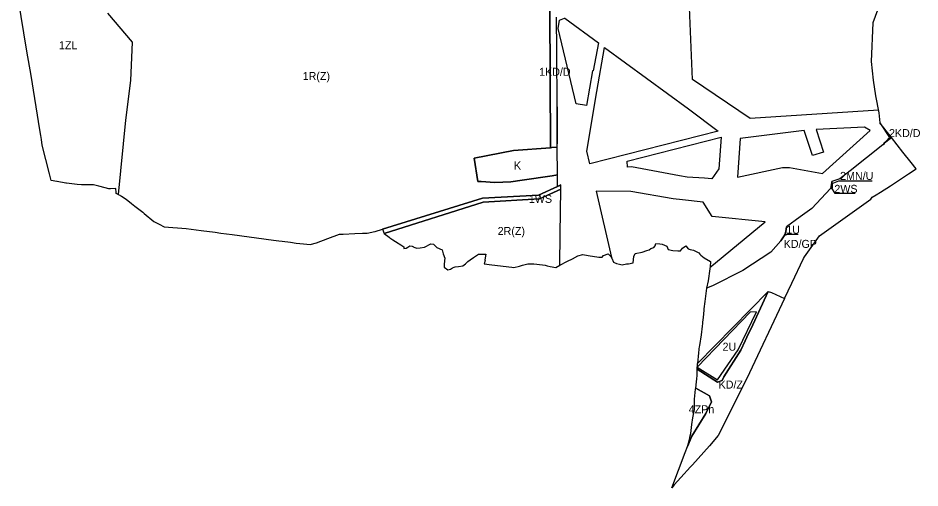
# Model space of a CAD drawing. Extents: x 7416449 to 7417931, y 5540122 to 5541628.
# Drawn here: x 7416476 to 7417829, y 5540122 to 5540827 of the extents above; entities that cross this region are included whole.
import ezdxf

# ---------------------------------------------------------------- set-up
doc = ezdxf.new("R2010")
doc.units = 0
for name, color, linetype in [('linie_rozgraniczajace', 7, 'Continuous'), ('linie_zabudowy_nieprzekraczalne', 7, 'Continuous'), ('oznaczenia_przeznaczen', 7, 'Continuous')]:
    doc.layers.add(name, color=color, linetype=linetype)

msp = doc.modelspace()

# ---------------------------------------------------------------- linework, layer by layer
at = {"layer": 'linie_rozgraniczajace'}
for p, q in [((7417767.1, 5540684.7), (7417768.6, 5540669.9)), ((7417284.7, 5540633.3), (7417284.6, 5540638.3)), ((7417708.7, 5540586), (7417696.7, 5540581.8)), ((7417285.1, 5540574.5), (7417290.1, 5540576.5)), ((7417696.7, 5540581.8), (7417695.7, 5540577.3)), ((7417649.1, 5540529), (7417628.3, 5540514.1))]:
    msp.add_line(p, q, dxfattribs=at)
for points in [[(7417779.8, 5540880), (7417778.8, 5540877.1), (7417757.9, 5540819.8), (7417755.5, 5540761.9), (7417758.6, 5540733.8), (7417761.8, 5540710.2), (7417767.1, 5540684.7)], [(7416610.1, 5540833.9), (7416647.2, 5540790.9), (7416644.6, 5540733.1), (7416637.1, 5540673.9), (7416626.1, 5540562.5), (7416623.4, 5540563.8), (7416623.2, 5540565.5), (7416622.8, 5540571.5), (7416614.6, 5540571), (7416612.4, 5540570.9), (7416606.9, 5540572.4), (7416597.2, 5540575), (7416589.4, 5540577), (7416582, 5540577), (7416575.2, 5540576.9), (7416571.1, 5540576.8), (7416564.8, 5540577.5), (7416548.9, 5540579.1), (7416547.7, 5540579.3), (7416534.5, 5540581.8), (7416534.2, 5540581.8), (7416525.9, 5540583.5), (7416523.4, 5540593.5), (7416512.3, 5540636.5), (7416511, 5540644.9), (7416510, 5540650.6), (7416508.6, 5540659.3), (7416495.5, 5540740.5), (7416489.4, 5540777.1), (7416476, 5540856.9)], [(7417283.6, 5540848.8), (7417270.5, 5540858.3), (7417273.7, 5540840.7), (7417274.7, 5540632.5), (7417276.7, 5540632.7), (7417284.7, 5540633.3)], [(7417285, 5540591.6), (7417277, 5540590.4), (7417232.2, 5540583.7), (7417214.9, 5540581.4), (7417191.2, 5540580.5), (7417170.7, 5540581.8), (7417165.7, 5540581.6), (7417160, 5540616.7), (7417218.9, 5540628.1), (7417274.7, 5540632.5), (7417273.7, 5540840.7)], [(7416610.1, 5540833.9), (7416647.2, 5540790.9), (7416644.6, 5540733.1), (7416637.1, 5540673.9), (7416626.1, 5540562.5), (7416628.5, 5540561.3), (7416629.4, 5540560.9), (7416631.3, 5540559.7), (7416638.3, 5540555.4), (7416646.4, 5540548.8), (7416651.2, 5540544.8), (7416663, 5540535.7), (7416665.4, 5540533.7), (7416679.8, 5540522.1), (7416684.6, 5540519.4), (7416687.7, 5540517.7), (7416695.4, 5540514), (7416728.2, 5540511.2), (7416750.4, 5540508.6), (7416771.5, 5540505.8), (7416780.3, 5540504.4), (7416797.1, 5540502.4), (7416859.1, 5540494), (7416867, 5540492.9), (7416872.1, 5540492.6), (7416884.6, 5540490.7), (7416893.3, 5540489.3), (7416904.1, 5540488.3), (7416914.3, 5540487.2), (7416923.4, 5540489.9), (7416940.8, 5540496.3), (7416958.1, 5540502.8), (7416963.4, 5540503), (7416981.3, 5540503.8), (7416992.6, 5540504.3), (7416999.7, 5540504.6), (7417010.9, 5540506.7), (7417011.7, 5540506.9), (7417022.8, 5540510.3), (7417172.7, 5540556.7), (7417256.8, 5540561.3), (7417285.1, 5540574.5), (7417285, 5540587.6), (7417285, 5540591.6)], [(7417284.6, 5540638.3), (7417284.4, 5540693.8), (7417284, 5540777.7), (7417283.8, 5540828), (7417283.8, 5540828)], [(7417284.4, 5540693.8), (7417284.4, 5540693.8), (7417284.6, 5540638.3)], [(7417284.6, 5540638.3), (7417284.4, 5540693.8), (7417284.4, 5540693.8)], [(7417773.1, 5540636.8), (7417773.8, 5540637.5), (7417775.7, 5540639.6), (7417785.9, 5540647.8), (7417768.6, 5540669.9)], [(7417768.6, 5540669.9), (7417783.2, 5540647.7), (7417773.1, 5540636.8)], [(7417563.1, 5540448.2), (7417517.4, 5540425.5), (7417508.7, 5540421.9), (7417507.8, 5540417.9), (7417506, 5540401.8), (7417504.6, 5540390.8), (7417504.4, 5540389.1), (7417503.9, 5540383.7), (7417503.3, 5540377.8), (7417502.5, 5540371), (7417502.4, 5540370.2), (7417502.3, 5540369.2), (7417501.8, 5540365.1), (7417500.3, 5540352.2), (7417498, 5540336), (7417497.7, 5540334.2), (7417497.2, 5540330.8), (7417497.1, 5540330), (7417496.3, 5540324.8), (7417494.9, 5540309), (7417601.1, 5540416.7), (7417606.1, 5540415.5), (7417625.6, 5540406.3), (7417636.5, 5540429.4), (7417654.1, 5540466.5), (7417655.3, 5540469), (7417677.8, 5540500.4), (7417755, 5540555.2), (7417755.2, 5540555.4), (7417757.2, 5540558.2), (7417763.2, 5540561.7), (7417769.6, 5540566), (7417784.5, 5540575.3), (7417811.4, 5540593.1), (7417822.8, 5540600.7), (7417815.5, 5540610.1), (7417803.2, 5540625.8), (7417785.9, 5540647.8), (7417775.7, 5540639.6), (7417773.8, 5540637.5), (7417773.1, 5540636.8), (7417748.5, 5540617.2), (7417724, 5540597.7), (7417708.7, 5540586)], [(7417284.7, 5540633.3), (7417276.7, 5540632.7), (7417274.7, 5540632.5), (7417218.9, 5540628.1), (7417160, 5540616.7), (7417165.7, 5540581.6), (7417170.7, 5540581.8), (7417191.2, 5540580.5), (7417214.9, 5540581.4), (7417232.2, 5540583.7), (7417277, 5540590.4), (7417285, 5540591.6), (7417284.7, 5540633.3)], [(7417290.1, 5540576.5), (7417285.1, 5540574.5), (7417256.8, 5540561.3), (7417172.7, 5540556.7), (7417022.8, 5540510.3), (7417025.1, 5540503.8), (7417173.7, 5540550.6), (7417258, 5540555.8), (7417290.1, 5540570.4)], [(7417290.1, 5540570.4), (7417258, 5540555.8), (7417173.7, 5540550.6), (7417025.1, 5540503.8), (7417032.7, 5540498.3), (7417033.7, 5540497.6), (7417037.9, 5540494.5), (7417046, 5540489.5), (7417047.7, 5540488.4), (7417049.9, 5540487), (7417054.4, 5540483.9), (7417054.5, 5540481.3), (7417058.3, 5540481.9), (7417060.8, 5540483.5), (7417063.8, 5540485.2), (7417066.9, 5540485.1), (7417069.1, 5540483.7), (7417069.7, 5540483.3), (7417073.9, 5540481.9), (7417079.1, 5540482.5), (7417085.8, 5540483.6), (7417095, 5540488.6), (7417098.9, 5540487.8), (7417103.9, 5540482.7), (7417112.2, 5540479.6), (7417113.7, 5540473.6), (7417116, 5540466.7), (7417115.7, 5540463.5), (7417115.7, 5540462.9), (7417115.1, 5540457.2), (7417115, 5540453.3), (7417120.7, 5540449.3), (7417124.7, 5540450.6), (7417127.7, 5540452.2), (7417130, 5540453.2), (7417131.6, 5540454), (7417136.4, 5540454.2), (7417142.9, 5540455.6), (7417147.2, 5540458.6), (7417150.6, 5540461.7), (7417154.2, 5540464.4), (7417159.3, 5540468), (7417166.8, 5540472.9), (7417172.3, 5540472.7), (7417177.4, 5540472.8), (7417176.2, 5540464.6), (7417176.6, 5540463.5), (7417175, 5540458.5), (7417186.5, 5540457), (7417216.8, 5540453.2), (7417219.8, 5540452.8), (7417228.3, 5540455), (7417232.6, 5540456.2), (7417240.4, 5540458.5), (7417249.8, 5540458.4), (7417254.3, 5540457.9), (7417266.5, 5540456.3), (7417269.7, 5540455.5), (7417274.1, 5540454.6), (7417282.6, 5540452.9), (7417288.7, 5540456.3)], [(7417290.1, 5540576.5), (7417290.1, 5540576.7), (7417285.1, 5540574.5)], [(7417288.7, 5540456.3), (7417289.3, 5540502.7), (7417290.1, 5540570.4)], [(7417290.1, 5540570.4), (7417290.1, 5540571.1), (7417290.1, 5540576.5)], [(7417696.7, 5540581.8), (7417696.9, 5540577.4), (7417697.1, 5540571.8), (7417694.5, 5540571.1), (7417680.6, 5540556.3), (7417666.6, 5540541.5), (7417649.1, 5540529)], [(7417694.4, 5540571.1), (7417694.5, 5540571.1), (7417697.1, 5540571.8), (7417696.9, 5540577.4), (7417695.7, 5540577.3)], [(7417695.7, 5540577.3), (7417694.4, 5540571.2), (7417694.4, 5540571.1)], [(7417695.7, 5540577.3), (7417696.9, 5540577.4), (7417696.7, 5540581.8)], [(7417731.7, 5540563.9), (7417701.3, 5540563.9), (7417695.9, 5540572.8)], [(7417756.8, 5540582.1), (7417706.7, 5540582.1), (7417696.4, 5540578.1)], [(7417620, 5540492.7), (7417626.9, 5540503.2), (7417628.3, 5540514.1)], [(7417628.3, 5540514.1), (7417625.8, 5540502.7), (7417620, 5540492.7)], [(7417628.3, 5540514.1), (7417626.9, 5540503.2), (7417620, 5540492.7)], [(7417646, 5540502.3), (7417630, 5540502.3), (7417625.1, 5540501.1)], [(7417288.7, 5540456.3), (7417300.1, 5540462.4), (7417307.4, 5540466), (7417315.5, 5540470.2), (7417323.2, 5540472.4), (7417331, 5540471.1), (7417346.8, 5540468.3), (7417352.2, 5540468.3), (7417354, 5540470.9), (7417361.2, 5540473.2), (7417364.8, 5540469.6), (7417366.5, 5540466.8), (7417369, 5540460.7), (7417373.7, 5540458.7), (7417378.2, 5540457.8), (7417381.9, 5540457.1), (7417388.3, 5540458.4), (7417391.4, 5540458.5), (7417398.7, 5540459.9), (7417399.3, 5540469.4), (7417401.3, 5540474.1), (7417412.1, 5540475.7), (7417419.2, 5540478.5), (7417422.6, 5540479.6), (7417424.8, 5540481.2), (7417429.6, 5540482.9), (7417431.5, 5540485.5), (7417432.7, 5540488.8), (7417438.6, 5540488.2), (7417442, 5540487.9), (7417448.9, 5540484.9), (7417450.9, 5540479.8), (7417457.8, 5540478.6), (7417465.6, 5540477.7), (7417469.3, 5540478.1), (7417472.6, 5540481.8), (7417477.7, 5540485.2), (7417480.8, 5540480.9), (7417484.2, 5540480), (7417489, 5540478.8), (7417494.1, 5540476.3), (7417497, 5540474.9), (7417498.7, 5540472.8), (7417499.9, 5540471.4), (7417505.2, 5540467.4), (7417514.7, 5540462.1), (7417513.8, 5540453.7), (7417513.4, 5540451), (7417511.1, 5540432.7), (7417508.7, 5540421.9)], [(7417620, 5540492.7), (7417604.9, 5540476), (7417563.1, 5540448.2)], [(7417331, 5540471.1), (7417331, 5540471.1), (7417331, 5540471.1)], [(7417331, 5540471.1), (7417331, 5540471.1), (7417331, 5540471.1), (7417331, 5540471.1)]]:
    msp.add_lwpolyline(points, dxfattribs=at)
for points in [[(7417456.5, 5540122.5), (7417476.6, 5540175.4), (7417480, 5540184.5), (7417486.3, 5540200.2), (7417507.5, 5540234), (7417516.2, 5540251.5), (7417512.9, 5540260.8), (7417492.4, 5540272.3), (7417493.4, 5540281.4), (7417493.9, 5540286.1), (7417494.4, 5540290.8), (7417494.5, 5540295.2), (7417494.6, 5540300.3), (7417525.2, 5540281.1), (7417532.1, 5540283.6), (7417534.7, 5540289), (7417560.2, 5540329), (7417566.3, 5540343.1), (7417571.7, 5540353.9), (7417575, 5540360.4), (7417601.1, 5540416.7), (7417606.1, 5540415.5), (7417625.6, 5540406.3), (7417569, 5540286.5), (7417526.1, 5540200.9), (7417512.9, 5540185.8), (7417487.4, 5540157), (7417484.7, 5540154.1), (7417470.1, 5540138.2), (7417460.1, 5540127.1)], [(7417494.6, 5540300.3), (7417494.8, 5540308), (7417494.9, 5540309), (7417601.1, 5540416.7), (7417575, 5540360.4), (7417571.7, 5540353.9), (7417566.3, 5540343.1), (7417560.2, 5540329), (7417534.7, 5540289), (7417532.1, 5540283.6), (7417525.2, 5540281.1)], [(7417480, 5540184.5), (7417481.9, 5540191.3), (7417483.4, 5540197.7), (7417483.5, 5540198.5), (7417484.8, 5540204.3), (7417486.3, 5540217.7), (7417487.8, 5540227.6), (7417490.4, 5540240.3), (7417490.3, 5540252.9), (7417490.6, 5540255.7), (7417492.2, 5540270.4), (7417492.4, 5540272.3), (7417512.9, 5540260.8), (7417516.2, 5540251.5), (7417507.5, 5540234), (7417486.3, 5540200.2)]]:
    msp.add_lwpolyline(points, close=True, dxfattribs=at)
at = {"layer": 'linie_zabudowy_nieprzekraczalne'}
for points in [[(7417766.3, 5540688.7), (7417573.8, 5540676), (7417487.3, 5540734.5), (7417480.1, 5540915.2), (7417493.9, 5540922.4), (7417586.3, 5540948.2), (7417739.1, 5540951.5), (7417778.8, 5540877)], [(7417346.6, 5540789.5), (7417338.4, 5540747.5), (7417337.4, 5540747.7), (7417328.4, 5540695.5), (7417312.9, 5540698.2), (7417286.3, 5540811.2), (7417288, 5540823.8), (7417295.5, 5540826.6), (7417296, 5540826.6), (7417346.6, 5540789.5)], [(7417355.7, 5540782.9), (7417481.3, 5540690.7), (7417525.8, 5540657.3), (7417333.5, 5540608.3), (7417329.1, 5540627.2), (7417343.8, 5540716.8), (7417355.7, 5540782.9)], [(7417555.1, 5540588.5), (7417622.7, 5540602.9), (7417632.8, 5540602.8), (7417682.4, 5540593.6), (7417753.8, 5540658.2), (7417745.5, 5540663.1), (7417672.8, 5540659.6), (7417683.8, 5540626), (7417667.5, 5540620.7), (7417655.2, 5540658.5), (7417559.2, 5540646.5), (7417555.1, 5540588.5)], [(7417530.7, 5540648.2), (7417527.2, 5540600.6), (7417516.4, 5540585.8), (7417505.7, 5540586.6), (7417479.3, 5540588.5), (7417468.2, 5540590.2), (7417396, 5540603.6), (7417389.9, 5540603.5), (7417389.5, 5540612.2), (7417530.7, 5540648.2)], [(7417513.6, 5540452.7), (7417596.6, 5540521.2), (7417516.9, 5540529.3), (7417503.5, 5540550.7), (7417472.7, 5540554.1), (7417458.5, 5540555.6), (7417394.8, 5540566.7), (7417343, 5540567.2), (7417365.9, 5540467.7)], [(7417494.7, 5540303.5), (7417525.1, 5540284.3), (7417555.8, 5540329.7), (7417583.3, 5540386.4), (7417574, 5540386.2), (7417495.1, 5540304)]]:
    msp.add_lwpolyline(points, dxfattribs=at)

# ---------------------------------------------------------------- texts
at = {"layer": 'oznaczenia_przeznaczen'}
for s, p in [('1ZL', (7416537.4, 5540780.1)), ('1R(Z)', (7416902.9, 5540733.9)), ('1KD/D', (7417257.5, 5540740.2)), ('2KD/D', (7417782.2, 5540648.4)), ('K', (7417219.7, 5540599.8)), ('2MN/U', (7417708.9, 5540584.2)), ('2WS', (7417700.3, 5540564.8)), ('1WS', (7417242.1, 5540549.8)), ('1U', (7417628.2, 5540503.6)), ('2R(Z)', (7417195.3, 5540501.6)), ('KD/GP', (7417624.3, 5540482.3)), ('2U', (7417532.6, 5540328.2)), ('KD/Z', (7417526.7, 5540271.4)), ('4ZPn', (7417481.8, 5540234.4))]:
    msp.add_text(s, height=12, dxfattribs=at).set_placement(p)

doc.saveas('drawing.dxf')
